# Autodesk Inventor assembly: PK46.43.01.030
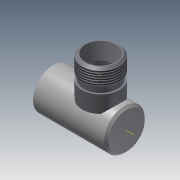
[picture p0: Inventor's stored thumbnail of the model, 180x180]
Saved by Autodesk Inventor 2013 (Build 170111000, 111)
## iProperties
Shininess: 64.0
Length Units: 11269
Angle Units: 11279
Time Units: 11290
Mass Units: 11283
Length Display Precision: 3
Angle Display Precision: 2
Compacted: True
Created: 2004-12
Part Number: PK46.43.01.030
Document SubType Name: Assembly
Designer: ELarisa
Manufacturer: Standard
Standards Organization: Custom
Density: 0.0
Volumn: 0.0
Area: 0.0
PropertySet Name: Model Information
Control State: 0
Master: False
Checked Out: False
Checked Out Date: 2008-10-09
Last Check In Date: 2008-10-09
Author: ELarisa
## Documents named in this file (3)
- D:\FrontLoaderVault\Data\Assy, Chassis, Front\PK46.43.01.030.iam
- D:\FrontLoaderVault\Data\Assy, Chassis, Front\PK46.43.01.031.ipt
- D:\FrontLoaderVault\Data\Assy, Chassis, Front\027.03.02.007.ipt
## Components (2 placed, 2 different names)
1. PK46.43.01.031:1 — Insert:1
2. 027.03.02.007:1 — Insert:1
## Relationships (1: Insert 1)
- Insert:1: PK46.43.01.031:1 ↔ 027.03.02.007:1
